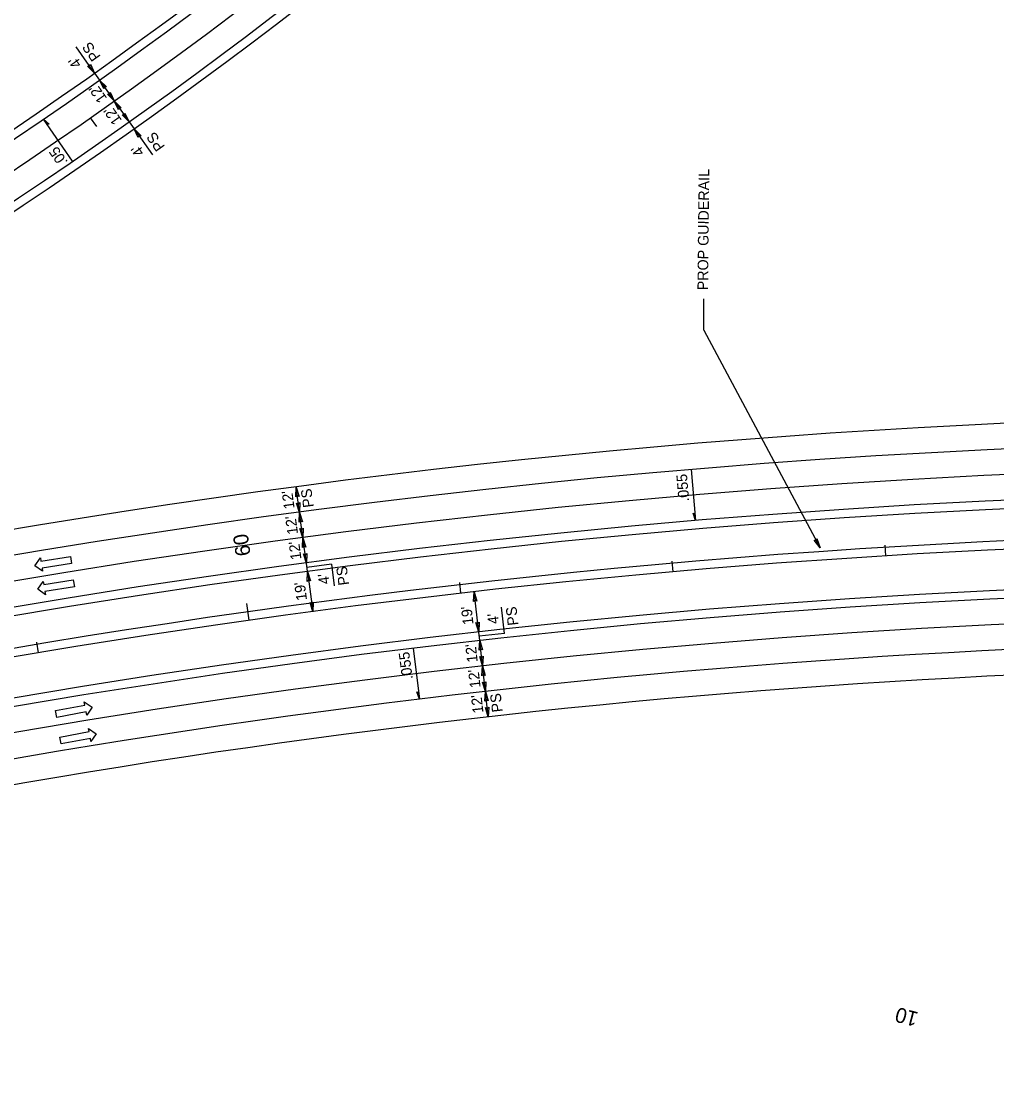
# Model space of a CAD drawing. Extents: x 2389694 to 2405615, y 547005 to 573532.
# Drawn here: x 2394188 to 2394645.3, y 553999 to 554498.2 of the extents above; entities that cross this region are included whole.
import ezdxf

# ---------------------------------------------------------------- set-up
doc = ezdxf.new("R2010")
doc.units = 0
for name, color, linetype in [('Prop Cable Guiderail Double Face', 7, 'Continuous'), ('Prop Dimension', 7, 'Continuous'), ('Prop Dimension Text', 7, 'Continuous'), ('Prop DSN Text', 7, 'Continuous'), ('Prop EOT', 7, 'Continuous'), ('Prop Horizontal Alignment', 7, 'Continuous'), ('Prop Horizontal Alignment Curve and Spiral Data', 7, 'Continuous'), ('Prop Horizontal Alignment Tick Large', 7, 'Continuous'), ('Prop Horizontal Alignment Tick Small', 7, 'Continuous'), ('Prop Lane Arrow Through CELL', 7, 'Continuous'), ('Prop Lane Lines', 7, 'Continuous'), ('Prop Super Arrow 1 Lane CELL', 7, 'Continuous'), ('Prop Superelevation Label', 7, 'Continuous')]:
    doc.layers.add(name, color=color, linetype=linetype)

msp = doc.modelspace()

# ---------------------------------------------------------------- linework, layer by layer
at = {"layer": 'Prop Cable Guiderail Double Face'}
msp.add_arc((2394828.31, 550434.92), 3824, 87.04844, 123.9393, dxfattribs=at)
at = {"layer": 'Prop Dimension'}
for p, q in [((2394222.39, 554473.9), (2394213.73, 554486.14)), ((2394222.39, 554473.9), (2394224.71, 554470.64)), ((2394224.71, 554470.64), (2394231.64, 554460.84)), ((2394231.64, 554460.84), (2394238.57, 554451.05)), ((2394238.57, 554451.05), (2394240.89, 554447.78)), ((2394240.89, 554447.78), (2394249.55, 554435.54)), ((2394507.98, 554353.36), (2394507.98, 554368.14)), ((2394507.98, 554353.36), (2394562.52, 554251.52)), ((2394318.45, 554268.05), (2394316.84, 554279.94)), ((2394320.07, 554256.16), (2394318.45, 554268.05)), ((2394321.68, 554244.27), (2394320.07, 554256.16)), ((2394322.22, 554240.3), (2394321.68, 554244.27)), ((2394333.37, 554243.84), (2394321.95, 554242.29)), ((2394333.37, 554243.84), (2394334.74, 554233.7)), ((2394322.22, 554240.3), (2394324.77, 554221.48)), ((2394402.47, 554211.99), (2394400.34, 554230.87)), ((2394414.49, 554211.37), (2394413.11, 554223.63)), ((2394402.92, 554208.01), (2394402.47, 554211.99)), ((2394414.49, 554211.37), (2394402.69, 554210.04)), ((2394404.26, 554196.09), (2394402.92, 554208.01)), ((2394405.6, 554184.16), (2394404.26, 554196.09)), ((2394406.95, 554172.24), (2394405.6, 554184.16))]:
    msp.add_line(p, q, dxfattribs=at)
for points in [[(2394220.43, 554478.02), (2394222.39, 554473.9), (2394219.13, 554477.13), (2394220.11, 554477.12)], [(2394226.67, 554466.51), (2394224.71, 554470.64), (2394227.97, 554467.4), (2394226.99, 554467.41)], [(2394229.67, 554464.96), (2394231.64, 554460.84), (2394228.37, 554464.07), (2394229.36, 554464.07)], [(2394233.61, 554456.72), (2394231.64, 554460.84), (2394234.91, 554457.61), (2394233.92, 554457.62)], [(2394236.61, 554455.17), (2394238.57, 554451.05), (2394235.31, 554454.28), (2394236.29, 554454.27)], [(2394242.85, 554443.66), (2394240.89, 554447.78), (2394244.15, 554444.55), (2394243.17, 554444.56)], [(2394316.67, 554275.38), (2394316.84, 554279.94), (2394318.24, 554275.56), (2394317.37, 554276.03)], [(2394318.61, 554272.61), (2394318.45, 554268.05), (2394317.05, 554272.43), (2394317.92, 554271.96)], [(2394318.29, 554263.49), (2394318.45, 554268.05), (2394319.85, 554263.67), (2394318.98, 554264.14)], [(2394320.23, 554260.72), (2394320.07, 554256.16), (2394318.66, 554260.53), (2394319.53, 554260.07)], [(2394319.9, 554251.6), (2394320.07, 554256.16), (2394321.47, 554251.78), (2394320.6, 554252.24)], [(2394561.03, 554255.84), (2394562.52, 554251.52), (2394559.64, 554255.1), (2394560.62, 554254.98)], [(2394321.84, 554248.83), (2394321.68, 554244.27), (2394320.28, 554248.64), (2394321.15, 554248.18)], [(2394322.05, 554235.74), (2394322.22, 554240.3), (2394323.62, 554235.93), (2394322.75, 554236.39)], [(2394400.07, 554226.31), (2394400.34, 554230.87), (2394401.64, 554226.46), (2394400.78, 554226.94)], [(2394324.93, 554226.04), (2394324.77, 554221.48), (2394323.37, 554225.85), (2394324.24, 554225.39)], [(2394402.73, 554216.54), (2394402.47, 554211.99), (2394401.16, 554216.39), (2394402.02, 554215.91)], [(2394402.65, 554203.45), (2394402.92, 554208.01), (2394404.22, 554203.6), (2394403.36, 554204.09)], [(2394404.53, 554200.65), (2394404.26, 554196.09), (2394402.96, 554200.49), (2394403.82, 554200.01)], [(2394403.99, 554191.53), (2394404.26, 554196.09), (2394405.56, 554191.68), (2394404.7, 554192.16)], [(2394405.87, 554188.72), (2394405.6, 554184.16), (2394404.3, 554188.57), (2394405.16, 554188.09)], [(2394405.34, 554179.6), (2394405.6, 554184.16), (2394406.91, 554179.76), (2394406.05, 554180.24)], [(2394407.21, 554176.8), (2394406.95, 554172.24), (2394405.65, 554176.64), (2394406.51, 554176.16)]]:
    msp.add_lwpolyline(points, close=True, dxfattribs=at)
at = {"layer": 'Prop EOT'}
for centre, radius, start, end in [((2392902.55, 556337.94), 2284, 296.10428, 342.30241), ((2392902.55, 556337.94), 2288, 296.10428, 342.30241), ((2392902.55, 556337.94), 2312, 296.10428, 342.30241), ((2392902.55, 556337.94), 2316, 296.10428, 342.30241), ((2394865.6, 554590.75), 1087, 256.52302, 12.63033), ((2394865.6, 554590.75), 1063, 256.52302, 12.63033), ((2394828.31, 550434.92), 3879, 67.475, 106.78848), ((2394828.31, 550434.92), 3867, 59.69891, 109.59769), ((2394828.31, 550434.92), 3843, 59.69891, 123.9393), ((2394828.31, 550434.92), 3839, 59.69891, 123.9393), ((2394828.31, 550434.92), 3801, 59.69891, 123.9393), ((2394828.31, 550434.92), 3797, 59.69891, 123.9393), ((2394828.31, 550434.92), 3773, 89.80344, 120.03622), ((2394828.31, 550434.92), 3761, 90.54697, 120.03622)]:
    msp.add_arc(centre, radius, start, end, dxfattribs=at)
at = {"layer": 'Prop Horizontal Alignment'}
for centre, radius, start, end in [((2392902.55, 556337.94), 2300, 296.10428, 342.30241), ((2394865.6, 554590.75), 1075, 256.52302, 12.63033), ((2394828.31, 550434.92), 3820, 59.69891, 123.9393)]:
    msp.add_arc(centre, radius, start, end, dxfattribs=at)
at = {"layer": 'Prop Horizontal Alignment Tick Large'}
msp.add_line((2394294.91, 554217.49), (2394293.79, 554225.41), dxfattribs=at)
at = {"layer": 'Prop Horizontal Alignment Tick Small'}
for p, q in [((2394220.39, 554452.93), (2394223.25, 554448.83)), ((2394220.39, 554452.93), (2394223.25, 554448.83)), ((2394593.31, 554247.68), (2394593, 554252.67)), ((2394493.59, 554240.22), (2394493.15, 554245.2)), ((2394394.1, 554230.16), (2394393.53, 554235.13)), ((2394196.08, 554202.23), (2394195.25, 554207.17))]:
    msp.add_line(p, q, dxfattribs=at)
at = {"layer": 'Prop Lane Arrow Through CELL'}
for p, q in [((2394197.26, 554245.21), (2394211.09, 554247.4)), ((2394211.09, 554247.4), (2394211.61, 554244.15)), ((2394194.42, 554243.04), (2394197.03, 554246.69)), ((2394198.02, 554240.47), (2394194.42, 554243.04)), ((2394197.03, 554246.69), (2394197.26, 554245.21)), ((2394211.61, 554244.15), (2394197.78, 554241.95)), ((2394197.78, 554241.95), (2394198.02, 554240.47)), ((2394195.72, 554232.06), (2394198.33, 554235.71)), ((2394198.33, 554235.71), (2394198.57, 554234.23)), ((2394198.57, 554234.23), (2394212.39, 554236.43)), ((2394212.91, 554233.17), (2394199.08, 554230.97)), ((2394212.39, 554236.43), (2394212.91, 554233.17)), ((2394199.32, 554229.49), (2394195.72, 554232.06)), ((2394199.08, 554230.97), (2394199.32, 554229.49)), ((2394204.04, 554175.2), (2394217.8, 554177.76)), ((2394217.8, 554177.76), (2394217.53, 554179.24)), ((2394217.53, 554179.24), (2394221.19, 554176.77)), ((2394204.64, 554171.95), (2394204.04, 554175.2)), ((2394218.41, 554174.52), (2394204.64, 554171.95)), ((2394218.68, 554173.05), (2394218.41, 554174.52)), ((2394221.19, 554176.77), (2394218.68, 554173.05)), ((2394206.04, 554162.78), (2394219.8, 554165.35)), ((2394206.64, 554159.54), (2394206.04, 554162.78)), ((2394219.8, 554165.35), (2394219.52, 554166.83)), ((2394219.52, 554166.83), (2394223.19, 554164.36)), ((2394223.19, 554164.36), (2394220.68, 554160.63)), ((2394220.4, 554162.11), (2394206.64, 554159.54)), ((2394220.68, 554160.63), (2394220.4, 554162.11))]:
    msp.add_line(p, q, dxfattribs=at)
at = {"layer": 'Prop Lane Lines'}
for radius in [3855, 3785]:
    msp.add_arc((2394828.31, 550434.92), radius, 59.69891, 123.9393, dxfattribs=at)
at = {"layer": 'Prop Super Arrow 1 Lane CELL'}
for p, q in [((2394212.1, 554432.58), (2394198.51, 554452.36)), ((2394502.03, 554288.13), (2394504.06, 554264.21)), ((2394371.75, 554204.37), (2394374.64, 554180.54))]:
    msp.add_line(p, q, dxfattribs=at)
for points in [[(2394198.51, 554452.36), (2394201.15, 554449.93), (2394200.18, 554449.93)], [(2394504.06, 554264.21), (2394502.96, 554267.63), (2394503.81, 554267.15)], [(2394374.64, 554180.54), (2394373.42, 554183.92), (2394374.28, 554183.47)]]:
    msp.add_lwpolyline(points, close=True, dxfattribs=at)

# ---------------------------------------------------------------- texts
at = {"layer": 'Prop Dimension Text'}
for s, rotation, p in [('PS', 125.3011, (2394225.47, 554481.66)), ("4'", 125.3011, (2394216.63, 554478.24)), ("12'", 125.3005, (2394228.44, 554462.1)), ("12'", 125.3003, (2394235.38, 554451.81)), ('PS', 125.3006, (2394255.61, 554439.48)), ("4'", 125.3006, (2394246.02, 554436.92)), ("12'", 97.7286, (2394316.18, 554269.92)), ('PS', 97.7286, (2394325.17, 554270.63)), ("12'", 97.7286, (2394317.79, 554258.03)), ("12'", 97.7286, (2394319.41, 554246.14)), ('PS', 97.7285, (2394341.74, 554234.19)), ("4'", 97.7285, (2394332.59, 554234.7)), ("19'", 97.7281, (2394322, 554227.05)), ("19'", 96.4326, (2394400.04, 554215.64)), ('PS', 96.4326, (2394421.09, 554215.29)), ("4'", 96.4326, (2394411.95, 554216)), ("12'", 96.433, (2394402.03, 554198.01)), ("12'", 96.433, (2394403.37, 554186.09)), ('PS', 96.433, (2394413.72, 554174.66)), ("12'", 96.433, (2394404.72, 554174.16))]:
    msp.add_text(s, height=5, rotation=rotation, dxfattribs=at).set_placement(p)
at = {"layer": 'Prop DSN Text'}
msp.add_text('PROP GUIDERAIL', height=5, rotation=89.4184, dxfattribs=at).set_placement((2394509.98, 554372.1))
at = {"layer": 'Prop Horizontal Alignment Curve and Spiral Data'}
for s, rotation, p in [('60', 98.0267, (2394295.58, 554248.06)), ('10', 165.3459, (2394608.94, 554033.7))]:
    msp.add_text(s, height=7, rotation=rotation, dxfattribs=at).set_placement(p)
at = {"layer": 'Prop Superelevation Label'}
for s, rotation, p in [('.05', 124.5009, (2394210.04, 554432.3)), ('.055', 94.8401, (2394501.15, 554273.28)), ('.055', 97.6234, (2394371.56, 554190.1))]:
    msp.add_text(s, height=5, rotation=rotation, dxfattribs=at).set_placement(p)

doc.saveas('drawing.dxf')
